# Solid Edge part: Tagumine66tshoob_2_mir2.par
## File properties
Author: KULL
Template: Iso Metric Part.par
Last saved by: KULL
Revision: 2
Application: Solid Edge
Accuracy: 0,990
Username: KULL
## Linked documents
Tagumine66tshoob_2.par
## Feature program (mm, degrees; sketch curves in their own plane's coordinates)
part copy "CopiedPart_1"
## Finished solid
Body 1: solid body, 15 faces, 15 edges, 0 vertices.
  Faces by surface: cylinder 6, plane 6, torus 2, blend 1
  Edges by curve: circle 13, intersection 2
Bounding box of the edges (mm; curved faces can reach further): 20.000 x 45.562 x 11.446, from (-352.46, -85.5617, 50.3651) to (-332.46, -40, 61.811).
Cylindrical faces by radius (mm): R2 x1, R2.5 x1, R2.5057 x1, R3 x2, R5 x1
Toroidal faces (ring radius, tube radius in mm): R4.6 r0.4 x2
Planar faces by outward normal: +x 1, -x 1, oblique 4
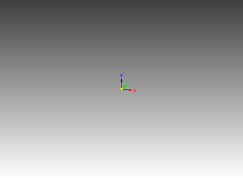
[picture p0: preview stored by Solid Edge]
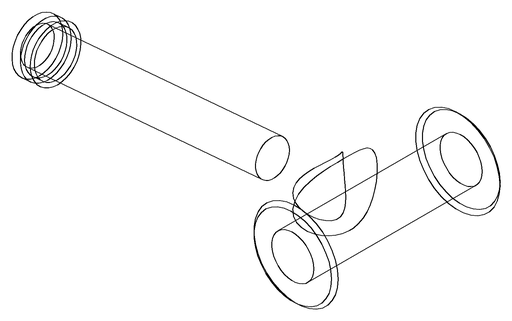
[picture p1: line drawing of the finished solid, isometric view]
